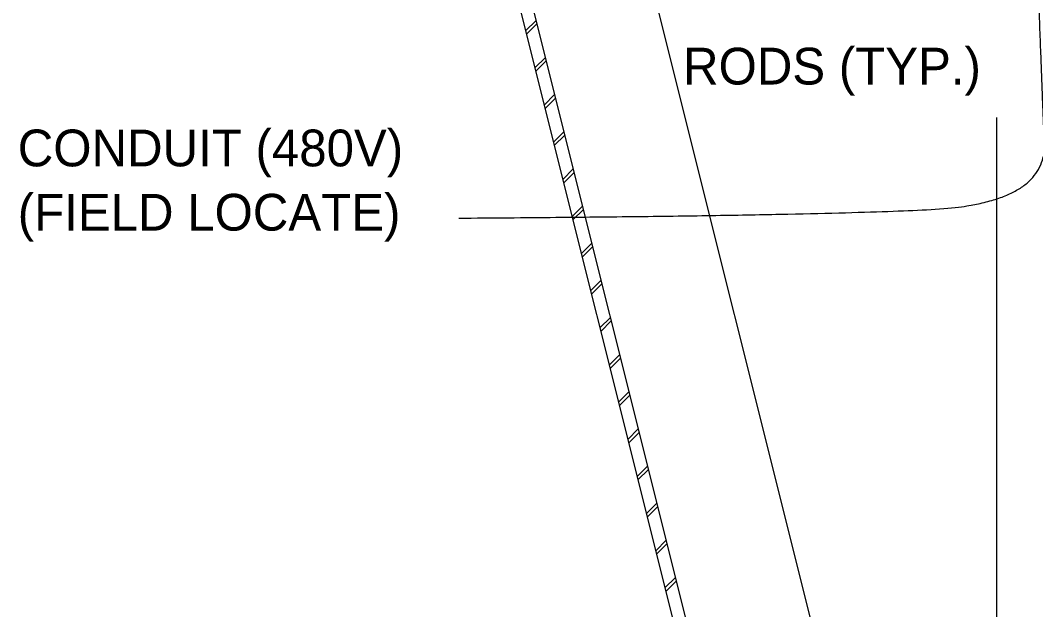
# Model space of a CAD drawing. Extents: x 927736.2 to 927809.6, y 636703.6 to 636757.7.
# Drawn here: x 927754.44 to 927764.73, y 636743.33 to 636749.31 of the extents above; entities that cross this region are included whole.
import ezdxf

# ---------------------------------------------------------------- set-up
doc = ezdxf.new("R2010")
doc.units = 0
doc.layers.add('DimLines_dp', color=7, linetype='Continuous')
doc.layers.add('Miscellaneous3', color=7, linetype='Continuous')

msp = doc.modelspace()

# ---------------------------------------------------------------- linework, layer by layer
at = {"layer": 'DimLines_dp'}
msp.add_open_spline([(927758.883, 636747.305), (927762.516, 636747.33), (927764.844, 636747.456), (927764.793, 636748.678), (927764.705, 636751.071)], degree=2, dxfattribs=at)
at = {"layer": 'Miscellaneous3'}
for p, q in [((927758.434, 636753.706), (927762.288, 636738.29)), ((927758.566, 636753.706), (927762.42, 636738.29)), ((927760.241, 636752.062), (927762.676, 636742.324)), ((927759.559, 636749.205), (927759.665, 636749.311)), ((927759.568, 636749.17), (927759.674, 636749.276)), ((927759.653, 636748.829), (927759.759, 636748.934)), ((927759.662, 636748.794), (927759.768, 636748.9)), ((927759.748, 636748.452), (927759.853, 636748.558)), ((927759.756, 636748.417), (927759.862, 636748.523)), ((927759.842, 636748.075), (927759.948, 636748.181)), ((927759.85, 636748.04), (927759.956, 636748.146)), ((927759.936, 636747.698), (927760.042, 636747.804)), ((927759.945, 636747.663), (927760.051, 636747.769)), ((927760.03, 636747.322), (927760.136, 636747.427)), ((927760.039, 636747.287), (927760.145, 636747.393)), ((927760.124, 636746.945), (927760.23, 636747.051)), ((927760.133, 636746.91), (927760.239, 636747.016)), ((927760.218, 636746.568), (927760.324, 636746.674)), ((927760.227, 636746.533), (927760.333, 636746.639)), ((927760.313, 636746.191), (927760.419, 636746.297)), ((927760.321, 636746.156), (927760.427, 636746.262)), ((927760.407, 636745.815), (927760.513, 636745.921)), ((927760.416, 636745.78), (927760.522, 636745.886)), ((927760.501, 636745.438), (927760.607, 636745.544)), ((927760.51, 636745.403), (927760.616, 636745.509)), ((927760.595, 636745.061), (927760.701, 636745.167)), ((927760.604, 636745.026), (927760.71, 636745.132)), ((927760.689, 636744.684), (927760.795, 636744.79)), ((927760.698, 636744.649), (927760.804, 636744.755)), ((927760.784, 636744.308), (927760.89, 636744.414)), ((927760.792, 636744.273), (927760.898, 636744.379)), ((927760.878, 636743.931), (927760.984, 636744.037)), ((927760.886, 636743.896), (927760.992, 636744.002)), ((927760.972, 636743.554), (927761.078, 636743.66)), ((927760.981, 636743.519), (927761.087, 636743.625))]:
    msp.add_line(p, q, dxfattribs=at)
msp.add_lwpolyline([(927764.332, 636748.324), (927764.332, 636743.124), (927766.449, 636743.124)], dxfattribs=at)

# ---------------------------------------------------------------- texts
at = {"layer": 'DimLines_dp'}
for s, p in [('RODS (TYP.)', (927761.155, 636748.66)), ('CONDUIT (480V)', (927754.41, 636747.83)), ('(FIELD LOCATE)', (927754.41, 636747.178))]:
    msp.add_text(s, height=0.37296, dxfattribs=at).set_placement(p)

doc.saveas('drawing.dxf')
